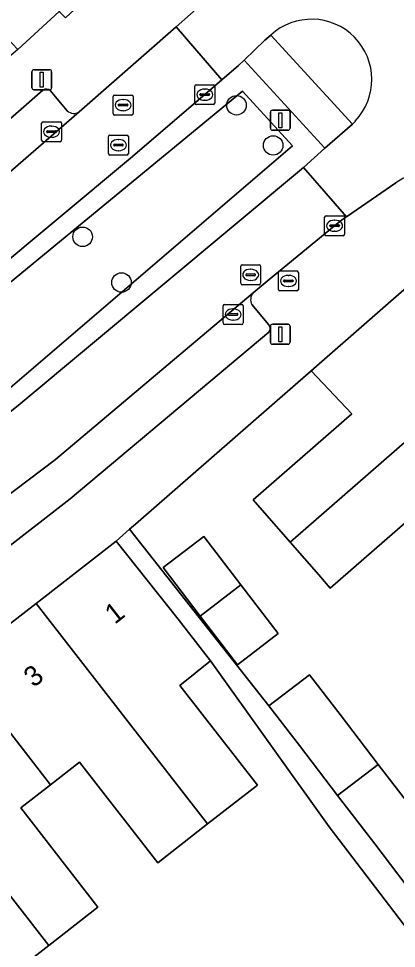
# Model space of a CAD drawing. Extents: x 159716 to 160783, y 383290 to 384031.
# Drawn here: x 160450.76 to 160469.71, y 383548.4 to 383595.01 of the extents above; entities that cross this region are included whole.
import ezdxf

# ---------------------------------------------------------------- set-up
doc = ezdxf.new("R2010")
doc.units = 0
for name, color, linetype in [('IMGEO_Boom', 7, 'Continuous'), ('IMGEO_Erf', 7, 'Continuous'), ('IMGEO_Groenvoorziening', 7, 'Continuous'), ('IMGEO_Kolk', 7, 'Continuous'), ('IMGEO_Lichtmast', 7, 'Continuous'), ('IMGEO_Muur', 7, 'Continuous'), ('IMGEO_Pand', 7, 'Continuous'), ('IMGEO_Pand_nummerreeks', 7, 'Continuous'), ('IMGEO_Parkeervlak_open', 7, 'Continuous'), ('IMGEO_Rijbaan_lokaal_open', 7, 'Continuous'), ('IMGEO_Rioolput', 7, 'Continuous'), ('IMGEO_Verkeerseiland_groen', 7, 'Continuous'), ('IMGEO_Voetpad_open', 7, 'Continuous')]:
    doc.layers.add(name, color=color, linetype=linetype)

msp = doc.modelspace()

# ---------------------------------------------------------------- linework, layer by layer
at = {"layer": 'IMGEO_Boom'}
for centre in [(160461.691, 383590.664), (160463.532, 383588.652), (160453.973, 383584.072), (160455.923, 383581.781)]:
    msp.add_circle(centre, 0.489, dxfattribs=at)
at = {"layer": 'IMGEO_Erf'}
for points in [[(160471.319, 383570.744), (160466.394, 383566.457), (160465.817, 383567.119), (160464.383, 383568.766), (160462.534, 383570.89), (160467.474, 383575.19), (160465.436, 383577.354), (160456.618, 383569.659), (160456.33, 383569.408), (160463.32, 383560.558), (160465.357, 383562.118), (160466.884, 383560.123), (160468.801, 383557.62), (160470.663, 383555.19)], [(160475.911, 383541.981), (160466.338, 383554.496), (160460.386, 383562.805), (160458.842, 383561.583), (160462.738, 383556.576), (160460.243, 383554.634), (160457.743, 383552.688), (160453.817, 383557.732), (160452.36, 383556.598), (160450.87, 383555.439), (160454.74, 383550.466), (160452.271, 383548.545), (160449.767, 383546.596), (160445.876, 383551.596), (160444.421, 383550.464), (160443.003, 383549.36), (160446.871, 383544.391)]]:
    msp.add_lwpolyline(points, dxfattribs=at)
msp.add_lwpolyline([(160461.741, 383562.62), (160459.876, 383565.055), (160458.011, 383567.49), (160460.047, 383569.05), (160461.912, 383566.615), (160463.777, 383564.179)], close=True, dxfattribs=at)
at = {"layer": 'IMGEO_Groenvoorziening'}
for points in [[(160441.098, 383568.136), (160443.878, 383570.259), (160449.157, 383574.362), (160450.745, 383575.611), (160465.056, 383587.54), (160466.119, 383588.51), (160462.076, 383592.933), (160461.787, 383592.665), (160460.963, 383591.947), (160460.102, 383591.197), (160456.376, 383588.007), (160445.683, 383579.106), (160439.333, 383574.187), (160436.59, 383572.062), (160419.524, 383558.843), (160420.216, 383557.971), (160438.33, 383572.13), (160446.182, 383578.368), (160461.987, 383591.376), (160464.497, 383588.63), (160449.031, 383575.404), (160429.985, 383560.714), (160408.787, 383544.408), (160399.76, 383538.598)], [(160461.987, 383591.376), (160446.182, 383578.368), (160438.33, 383572.13), (160420.216, 383557.971), (160419.524, 383558.843), (160417.152, 383557.006), (160417.838, 383556.217), (160406.387, 383547.75), (160398.414, 383542.841)], [(160399.76, 383538.598), (160408.787, 383544.408), (160429.985, 383560.714), (160449.031, 383575.404), (160464.497, 383588.63), (160461.987, 383591.376)]]:
    msp.add_lwpolyline(points, dxfattribs=at)
at = {"layer": 'IMGEO_Kolk'}
for p, q in [((160459.676, 383591.697), (160460.528, 383591.697)), ((160459.601, 383590.771), (160459.601, 383591.623)), ((160459.903, 383591.24), (160460.301, 383591.24)), ((160460.089, 383591.477), (160460.114, 383591.477)), ((160460.602, 383591.623), (160460.602, 383590.771)), ((160459.86, 383591.191), (160459.86, 383591.203)), ((160460.298, 383591.154), (160459.9, 383591.154)), ((160460.112, 383590.917), (160460.087, 383590.917)), ((160460.344, 383591.203), (160460.344, 383591.191)), ((160460.528, 383590.697), (160459.676, 383590.697)), ((160451.989, 383589.839), (160452.841, 383589.839)), ((160451.914, 383588.913), (160451.914, 383589.765)), ((160452.216, 383589.382), (160452.614, 383589.382)), ((160452.402, 383589.619), (160452.427, 383589.619)), ((160452.915, 383589.765), (160452.915, 383588.913)), ((160452.173, 383589.333), (160452.173, 383589.345)), ((160452.611, 383589.296), (160452.213, 383589.296)), ((160452.425, 383589.059), (160452.4, 383589.059)), ((160452.657, 383589.345), (160452.657, 383589.333)), ((160452.841, 383588.839), (160451.989, 383588.839)), ((160466.113, 383584.2), (160466.113, 383585.052)), ((160466.188, 383585.126), (160467.04, 383585.126)), ((160466.601, 383584.906), (160466.626, 383584.906)), ((160467.114, 383585.052), (160467.114, 383584.2)), ((160466.372, 383584.62), (160466.372, 383584.632)), ((160466.81, 383584.583), (160466.412, 383584.583)), ((160466.415, 383584.669), (160466.813, 383584.669)), ((160466.624, 383584.346), (160466.599, 383584.346)), ((160466.856, 383584.632), (160466.856, 383584.62)), ((160467.04, 383584.126), (160466.188, 383584.126)), ((160461.023, 383579.75), (160461.023, 383580.602)), ((160461.098, 383580.676), (160461.95, 383580.676)), ((160462.024, 383580.602), (160462.024, 383579.75)), ((160461.282, 383580.17), (160461.282, 383580.182)), ((160461.72, 383580.133), (160461.322, 383580.133)), ((160461.325, 383580.219), (160461.723, 383580.219)), ((160461.511, 383580.456), (160461.536, 383580.456)), ((160461.766, 383580.182), (160461.766, 383580.17)), ((160461.95, 383579.676), (160461.098, 383579.676)), ((160461.534, 383579.896), (160461.509, 383579.896))]:
    msp.add_line(p, q, dxfattribs=at)
for points in [[(160459.676, 383591.697), (160460.528, 383591.697)], [(160459.601, 383590.771), (160459.601, 383591.623)], [(160460.602, 383591.623), (160460.602, 383590.771)], [(160460.528, 383590.697), (160459.676, 383590.697)], [(160451.989, 383589.839), (160452.841, 383589.839)], [(160451.914, 383588.913), (160451.914, 383589.765)], [(160452.915, 383589.765), (160452.915, 383588.913)], [(160452.841, 383588.839), (160451.989, 383588.839)], [(160466.113, 383584.2), (160466.113, 383585.052)], [(160466.188, 383585.126), (160467.04, 383585.126)], [(160467.114, 383585.052), (160467.114, 383584.2)], [(160467.04, 383584.126), (160466.188, 383584.126)], [(160461.023, 383579.75), (160461.023, 383580.602)], [(160461.098, 383580.676), (160461.95, 383580.676)], [(160462.024, 383580.602), (160462.024, 383579.75)], [(160461.95, 383579.676), (160461.098, 383579.676)]]:
    msp.add_lwpolyline(points, dxfattribs=at)
for centre, radius, start, end in [((160459.678, 383591.621), 0.0765, 91.552, 178.448), ((160459.678, 383591.621), 0.0765, 91.552, 178.448), ((160460.526, 383591.621), 0.0765, 1.552, 88.448), ((160460.526, 383591.621), 0.0765, 1.552, 88.448), ((160459.9, 383591.2), 0.0403, 85.8775, 175.7526), ((160460.305, 383591.202), 0.0386, 1.7309, 96.639), ((160459.678, 383590.773), 0.0765, 181.552, 268.448), ((160459.678, 383590.773), 0.0765, 181.552, 268.448), ((160459.897, 383591.19), 0.0366, 178.938, 274.7102), ((160460.301, 383591.197), 0.043, 264.8664, 352.4533), ((160460.526, 383590.773), 0.0765, 271.552, 358.448), ((160460.526, 383590.773), 0.0765, 271.552, 358.448), ((160451.991, 383589.763), 0.0765, 91.552, 178.448), ((160451.991, 383589.763), 0.0765, 91.552, 178.448), ((160452.839, 383589.763), 0.0765, 1.552, 88.448), ((160452.839, 383589.763), 0.0765, 1.552, 88.448), ((160452.213, 383589.342), 0.0403, 85.8775, 175.7526), ((160452.618, 383589.344), 0.0386, 1.7309, 96.639), ((160451.991, 383588.915), 0.0765, 181.552, 268.448), ((160451.991, 383588.915), 0.0765, 181.552, 268.448), ((160452.21, 383589.332), 0.0366, 178.938, 274.7102), ((160452.614, 383589.339), 0.043, 264.8664, 352.4533), ((160452.839, 383588.915), 0.0765, 271.552, 358.448), ((160452.839, 383588.915), 0.0765, 271.552, 358.448), ((160466.19, 383585.05), 0.0765, 91.552, 178.448), ((160466.19, 383585.05), 0.0765, 91.552, 178.448), ((160467.038, 383585.05), 0.0765, 1.552, 88.448), ((160467.038, 383585.05), 0.0765, 1.552, 88.448), ((160466.412, 383584.629), 0.0403, 85.8775, 175.7526), ((160466.409, 383584.619), 0.0366, 178.938, 274.7102), ((160466.813, 383584.626), 0.043, 264.8664, 352.4533), ((160466.817, 383584.631), 0.0386, 1.7309, 96.639), ((160466.19, 383584.202), 0.0765, 181.552, 268.448), ((160466.19, 383584.202), 0.0765, 181.552, 268.448), ((160467.038, 383584.202), 0.0765, 271.552, 358.448), ((160467.038, 383584.202), 0.0765, 271.552, 358.448), ((160461.1, 383580.6), 0.0765, 91.552, 178.448), ((160461.1, 383580.6), 0.0765, 91.552, 178.448), ((160461.948, 383580.6), 0.0765, 1.552, 88.448), ((160461.948, 383580.6), 0.0765, 1.552, 88.448), ((160461.322, 383580.179), 0.0403, 85.8775, 175.7526), ((160461.319, 383580.169), 0.0366, 178.938, 274.7102), ((160461.723, 383580.176), 0.043, 264.8664, 352.4533), ((160461.727, 383580.181), 0.0386, 1.7309, 96.639), ((160461.1, 383579.752), 0.0765, 181.552, 268.448), ((160461.1, 383579.752), 0.0765, 181.552, 268.448), ((160461.948, 383579.752), 0.0765, 271.552, 358.448), ((160461.948, 383579.752), 0.0765, 271.552, 358.448)]:
    msp.add_arc(centre, radius, start, end, dxfattribs=at)
for centre, major_axis, ratio, start_param, end_param in [((160460.088, 383591.197), (-0.387, 0.002), 0.722429, 4.712389, 7.853982), ((160460.113, 383591.197), (-0.39, 0.002), 0.717154, 1.570796, 4.712389), ((160452.401, 383589.339), (-0.387, 0.002), 0.722429, 4.712389, 7.853982), ((160452.426, 383589.339), (-0.39, 0.002), 0.717154, 1.570796, 4.712389), ((160466.6, 383584.626), (-0.387, 0.002), 0.722429, 4.712389, 7.853982), ((160466.625, 383584.626), (-0.39, 0.002), 0.717154, 1.570796, 4.712389), ((160461.51, 383580.176), (-0.387, 0.002), 0.722429, 4.712389, 7.853982), ((160461.535, 383580.176), (-0.39, 0.002), 0.717154, 1.570796, 4.712389)]:
    msp.add_ellipse(centre, major_axis=major_axis, ratio=ratio, start_param=start_param, end_param=end_param, dxfattribs=at)
at = {"layer": 'IMGEO_Lichtmast'}
for p, q in [((160451.43, 383591.546), (160451.43, 383592.346)), ((160451.43, 383592.346), (160451.43, 383591.546)), ((160451.53, 383592.446), (160452.32, 383592.446)), ((160452.32, 383592.446), (160451.53, 383592.446)), ((160452.42, 383592.346), (160452.42, 383591.546)), ((160452.42, 383591.546), (160452.42, 383592.346)), ((160452.32, 383591.446), (160451.53, 383591.446)), ((160451.53, 383591.446), (160452.32, 383591.446)), ((160463.39, 383589.516), (160463.39, 383590.316)), ((160463.39, 383590.316), (160463.39, 383589.516)), ((160463.49, 383590.416), (160464.28, 383590.416)), ((160464.28, 383590.416), (160463.49, 383590.416)), ((160464.38, 383590.316), (160464.38, 383589.516)), ((160464.38, 383589.516), (160464.38, 383590.316)), ((160464.28, 383589.416), (160463.49, 383589.416)), ((160463.49, 383589.416), (160464.28, 383589.416)), ((160463.391, 383578.788), (160463.391, 383579.588)), ((160463.391, 383579.588), (160463.391, 383578.788)), ((160463.491, 383579.688), (160464.281, 383579.688)), ((160464.281, 383579.688), (160463.491, 383579.688)), ((160464.381, 383579.588), (160464.381, 383578.788)), ((160464.381, 383578.788), (160464.381, 383579.588)), ((160464.281, 383578.688), (160463.491, 383578.688)), ((160463.491, 383578.688), (160464.281, 383578.688))]:
    msp.add_line(p, q, dxfattribs=at)
for points in [[(160451.85, 383592.321), (160452, 383592.321), (160452, 383591.571), (160451.85, 383591.571), (160451.85, 383592.321)], [(160463.81, 383590.291), (160463.96, 383590.291), (160463.96, 383589.541), (160463.81, 383589.541), (160463.81, 383590.291)], [(160463.811, 383579.563), (160463.961, 383579.563), (160463.961, 383578.813), (160463.811, 383578.813), (160463.811, 383579.563)]]:
    msp.add_lwpolyline(points, dxfattribs=at)
for centre, start, end in [((160451.53, 383592.346), 90, 180), ((160451.53, 383592.346), 90, 180), ((160452.32, 383592.346), 0, 90), ((160452.32, 383592.346), 360, 90), ((160451.53, 383591.546), 180, 270), ((160451.53, 383591.546), 180, 270), ((160452.32, 383591.546), 270, 0), ((160452.32, 383591.546), 270, 0), ((160463.49, 383590.316), 90, 180), ((160463.49, 383590.316), 90, 180), ((160464.28, 383590.316), 0, 90), ((160464.28, 383590.316), 360, 90), ((160463.49, 383589.516), 180, 270), ((160463.49, 383589.516), 180, 270), ((160464.28, 383589.516), 270, 0), ((160464.28, 383589.516), 270, 0), ((160463.491, 383579.588), 90, 180), ((160463.491, 383579.588), 90, 180), ((160464.281, 383579.588), 0, 90), ((160464.281, 383579.588), 360, 90), ((160463.491, 383578.788), 180, 270), ((160463.491, 383578.788), 180, 270), ((160464.281, 383578.788), 270, 0), ((160464.281, 383578.788), 270, 0)]:
    msp.add_arc(centre, 0.1, start, end, dxfattribs=at)
at = {"layer": 'IMGEO_Muur'}
msp.add_lwpolyline([(160465.53, 383577.422), (160456.618, 383569.659)], dxfattribs=at)
at = {"layer": 'IMGEO_Pand'}
for points in [[(160456.328, 383598.598), (160452.391, 383602.844), (160441.972, 383593.226), (160443.909, 383591.127), (160448.722, 383595.569), (160450.731, 383593.456), (160452.802, 383595.359)], [(160474.958, 383577.974), (160471.15, 383582.344), (160465.436, 383577.354), (160467.474, 383575.19), (160462.534, 383570.89), (160464.383, 383568.766)], [(160478.672, 383573.711), (160474.958, 383577.974), (160464.383, 383568.766), (160465.817, 383567.119), (160466.394, 383566.457), (160471.319, 383570.744), (160473.02, 383568.79)], [(160459.876, 383565.055), (160461.912, 383566.615), (160460.047, 383569.05), (160458.011, 383567.49)], [(160460.386, 383562.805), (160458.759, 383564.903), (160455.652, 383568.805), (160451.637, 383565.693), (160460.243, 383554.634), (160462.738, 383556.576), (160458.842, 383561.583)], [(160461.912, 383566.615), (160459.876, 383565.055), (160461.741, 383562.62), (160463.777, 383564.179)], [(160451.637, 383565.693), (160447.673, 383562.621), (160452.36, 383556.598), (160453.817, 383557.732), (160457.743, 383552.688), (160460.243, 383554.634)], [(160452.36, 383556.598), (160447.673, 383562.621), (160443.709, 383559.549), (160452.271, 383548.545), (160454.74, 383550.466), (160450.87, 383555.439)], [(160463.32, 383560.558), (160464.848, 383558.563), (160466.765, 383556.06), (160468.801, 383557.62), (160466.884, 383560.123), (160465.357, 383562.118)], [(160443.709, 383559.549), (160439.743, 383556.475), (160444.421, 383550.464), (160445.876, 383551.596), (160449.767, 383546.596), (160452.271, 383548.545)], [(160468.801, 383557.62), (160466.765, 383556.06), (160468.627, 383553.63), (160470.211, 383551.561), (160472.248, 383553.121), (160470.663, 383555.19)]]:
    msp.add_lwpolyline(points, close=True, dxfattribs=at)
at = {"layer": 'IMGEO_Parkeervlak_open'}
for points in [[(160451.98, 383591.416), (160446.67, 383586.789), (160443.313, 383583.959), (160440.642, 383581.871), (160433.666, 383576.451), (160409.644, 383557.841)], [(160453.204, 383590.391), (160452.355, 383591.383)], [(160434.605, 383574.639), (160437.407, 383576.667), (160441.855, 383580.276), (160444.559, 383582.233), (160447.921, 383585.232), (160453.807, 383590.339)], [(160462.536, 383581.254), (160452.608, 383572.904), (160445.815, 383567.773), (160444.366, 383566.679), (160443.016, 383565.634), (160415.975, 383544.704)], [(160463.321, 383579.661), (160462.468, 383580.674)], [(160417.362, 383543.071), (160445.968, 383565.216), (160453.348, 383570.928), (160463.309, 383579.284)]]:
    msp.add_lwpolyline(points, dxfattribs=at)
for centre, radius, start, end in [((160452.15, 383591.204), 0.272, 41.116, 128.8259), ((160453.538, 383590.741), 0.484, 226.3471, 303.7955), ((160462.878, 383580.92), 0.478, 135.6807, 210.9455), ((160463.094, 383579.48), 0.29, 317.6692, 38.6845)]:
    msp.add_arc(centre, radius, start, end, dxfattribs=at)
at = {"layer": 'IMGEO_Rijbaan_lokaal_open'}
for points in [[(160460.103, 383595.872), (160458.661, 383594.596), (160460.963, 383591.947), (160461.787, 383592.665), (160462.076, 383592.933), (160463.114, 383593.925), (160463.409, 383594.184)], [(160467.653, 383589.872), (160467.507, 383589.719), (160466.119, 383588.51), (160465.056, 383587.54), (160467.208, 383585.075), (160469.692, 383586.773)]]:
    msp.add_lwpolyline(points, dxfattribs=at)
for points in [[(160460.963, 383591.947), (160458.661, 383594.596), (160453.807, 383590.339), (160447.921, 383585.232), (160444.559, 383582.233), (160441.855, 383580.276), (160437.407, 383576.667), (160439.333, 383574.187), (160445.683, 383579.106), (160456.376, 383588.007), (160460.102, 383591.197)], [(160462.536, 383581.254), (160463.326, 383581.931), (160466.614, 383584.626), (160466.966, 383584.91), (160467.208, 383585.075), (160465.056, 383587.54), (160450.745, 383575.611), (160449.157, 383574.362), (160443.878, 383570.259), (160445.815, 383567.773), (160452.608, 383572.904)]]:
    msp.add_lwpolyline(points, close=True, dxfattribs=at)
for centre, radius, start, end in [((160465.454, 383591.952), 3.027, 316.5846, 132.5047), ((160472.446, 383582.832), 4.808, 49.1527, 124.9472)]:
    msp.add_arc(centre, radius, start, end, dxfattribs=at)
at = {"layer": 'IMGEO_Rioolput'}
for p, q in [((160455.506, 383590.248), (160455.506, 383591.1)), ((160455.581, 383591.174), (160456.433, 383591.174)), ((160455.994, 383590.954), (160456.019, 383590.954)), ((160456.507, 383591.1), (160456.507, 383590.248)), ((160455.765, 383590.668), (160455.765, 383590.68)), ((160456.203, 383590.631), (160455.805, 383590.631)), ((160455.808, 383590.717), (160456.206, 383590.717)), ((160456.017, 383590.394), (160455.992, 383590.394)), ((160456.249, 383590.68), (160456.249, 383590.668)), ((160456.433, 383590.174), (160455.581, 383590.174)), ((160455.27, 383588.241), (160455.27, 383589.093)), ((160455.345, 383589.167), (160456.197, 383589.167)), ((160455.758, 383588.947), (160455.783, 383588.947)), ((160456.271, 383589.093), (160456.271, 383588.241)), ((160455.529, 383588.661), (160455.529, 383588.673)), ((160455.967, 383588.624), (160455.569, 383588.624)), ((160455.572, 383588.71), (160455.97, 383588.71)), ((160456.013, 383588.673), (160456.013, 383588.661)), ((160456.197, 383588.167), (160455.345, 383588.167)), ((160455.781, 383588.387), (160455.756, 383588.387)), ((160461.903, 383581.739), (160461.903, 383582.591)), ((160461.978, 383582.665), (160462.83, 383582.665)), ((160462.391, 383582.445), (160462.416, 383582.445)), ((160462.904, 383582.591), (160462.904, 383581.739)), ((160463.872, 383582.359), (160464.724, 383582.359)), ((160462.162, 383582.159), (160462.162, 383582.171)), ((160462.6, 383582.122), (160462.202, 383582.122)), ((160462.205, 383582.208), (160462.603, 383582.208)), ((160462.646, 383582.171), (160462.646, 383582.159)), ((160463.797, 383581.433), (160463.797, 383582.285)), ((160464.099, 383581.902), (160464.497, 383581.902)), ((160464.285, 383582.139), (160464.31, 383582.139)), ((160464.798, 383582.285), (160464.798, 383581.433)), ((160462.83, 383581.665), (160461.978, 383581.665)), ((160462.414, 383581.885), (160462.389, 383581.885)), ((160464.056, 383581.853), (160464.056, 383581.865)), ((160464.494, 383581.816), (160464.096, 383581.816)), ((160464.308, 383581.579), (160464.283, 383581.579)), ((160464.54, 383581.865), (160464.54, 383581.853)), ((160464.724, 383581.359), (160463.872, 383581.359))]:
    msp.add_line(p, q, dxfattribs=at)
for points in [[(160455.506, 383590.248), (160455.506, 383591.1)], [(160455.581, 383591.174), (160456.433, 383591.174)], [(160456.507, 383591.1), (160456.507, 383590.248)], [(160456.433, 383590.174), (160455.581, 383590.174)], [(160455.27, 383588.241), (160455.27, 383589.093)], [(160455.345, 383589.167), (160456.197, 383589.167)], [(160456.271, 383589.093), (160456.271, 383588.241)], [(160456.197, 383588.167), (160455.345, 383588.167)], [(160461.903, 383581.739), (160461.903, 383582.591)], [(160461.978, 383582.665), (160462.83, 383582.665)], [(160462.904, 383582.591), (160462.904, 383581.739)], [(160463.872, 383582.359), (160464.724, 383582.359)], [(160463.797, 383581.433), (160463.797, 383582.285)], [(160464.798, 383582.285), (160464.798, 383581.433)], [(160462.83, 383581.665), (160461.978, 383581.665)], [(160464.724, 383581.359), (160463.872, 383581.359)]]:
    msp.add_lwpolyline(points, dxfattribs=at)
for centre, radius, start, end in [((160455.583, 383591.098), 0.0765, 91.552, 178.448), ((160455.583, 383591.098), 0.0765, 91.552, 178.448), ((160456.431, 383591.098), 0.0765, 1.552, 88.448), ((160456.431, 383591.098), 0.0765, 1.552, 88.448), ((160455.805, 383590.677), 0.0403, 85.8775, 175.7526), ((160455.802, 383590.667), 0.0366, 178.938, 274.7102), ((160456.206, 383590.674), 0.043, 264.8664, 352.4533), ((160456.21, 383590.679), 0.0386, 1.7309, 96.639), ((160455.583, 383590.25), 0.0765, 181.552, 268.448), ((160455.583, 383590.25), 0.0765, 181.552, 268.448), ((160456.431, 383590.25), 0.0765, 271.552, 358.448), ((160456.431, 383590.25), 0.0765, 271.552, 358.448), ((160455.347, 383589.091), 0.0765, 91.552, 178.448), ((160455.347, 383589.091), 0.0765, 91.552, 178.448), ((160456.195, 383589.091), 0.0765, 1.552, 88.448), ((160456.195, 383589.091), 0.0765, 1.552, 88.448), ((160455.569, 383588.67), 0.0403, 85.8775, 175.7526), ((160455.566, 383588.66), 0.0366, 178.938, 274.7102), ((160455.97, 383588.667), 0.043, 264.8664, 352.4533), ((160455.974, 383588.672), 0.0386, 1.7309, 96.639), ((160455.347, 383588.243), 0.0765, 181.552, 268.448), ((160455.347, 383588.243), 0.0765, 181.552, 268.448), ((160456.195, 383588.243), 0.0765, 271.552, 358.448), ((160456.195, 383588.243), 0.0765, 271.552, 358.448), ((160461.98, 383582.589), 0.0765, 91.552, 178.448), ((160461.98, 383582.589), 0.0765, 91.552, 178.448), ((160462.828, 383582.589), 0.0765, 1.552, 88.448), ((160462.828, 383582.589), 0.0765, 1.552, 88.448), ((160463.874, 383582.283), 0.0765, 91.552, 178.448), ((160463.874, 383582.283), 0.0765, 91.552, 178.448), ((160464.722, 383582.283), 0.0765, 1.552, 88.448), ((160464.722, 383582.283), 0.0765, 1.552, 88.448), ((160462.202, 383582.168), 0.0403, 85.8775, 175.7526), ((160462.199, 383582.158), 0.0366, 178.938, 274.7102), ((160462.603, 383582.165), 0.043, 264.8664, 352.4533), ((160462.607, 383582.17), 0.0386, 1.7309, 96.639), ((160464.096, 383581.862), 0.0403, 85.8775, 175.7526), ((160464.501, 383581.864), 0.0386, 1.7309, 96.639), ((160461.98, 383581.741), 0.0765, 181.552, 268.448), ((160461.98, 383581.741), 0.0765, 181.552, 268.448), ((160462.828, 383581.741), 0.0765, 271.552, 358.448), ((160462.828, 383581.741), 0.0765, 271.552, 358.448), ((160463.874, 383581.435), 0.0765, 181.552, 268.448), ((160463.874, 383581.435), 0.0765, 181.552, 268.448), ((160464.093, 383581.852), 0.0366, 178.938, 274.7102), ((160464.497, 383581.859), 0.043, 264.8664, 352.4533), ((160464.722, 383581.435), 0.0765, 271.552, 358.448), ((160464.722, 383581.435), 0.0765, 271.552, 358.448)]:
    msp.add_arc(centre, radius, start, end, dxfattribs=at)
for centre, major_axis, ratio, start_param, end_param in [((160455.993, 383590.674), (-0.387, 0.002), 0.722429, 4.712389, 7.853982), ((160456.018, 383590.674), (-0.39, 0.002), 0.717154, 1.570796, 4.712389), ((160455.757, 383588.667), (-0.387, 0.002), 0.722429, 4.712389, 7.853982), ((160455.782, 383588.667), (-0.39, 0.002), 0.717154, 1.570796, 4.712389), ((160462.39, 383582.165), (-0.387, 0.002), 0.722429, 4.712389, 7.853982), ((160462.415, 383582.165), (-0.39, 0.002), 0.717154, 1.570796, 4.712389), ((160464.284, 383581.859), (-0.387, 0.002), 0.722429, 4.712389, 7.853982), ((160464.309, 383581.859), (-0.39, 0.002), 0.717154, 1.570796, 4.712389)]:
    msp.add_ellipse(centre, major_axis=major_axis, ratio=ratio, start_param=start_param, end_param=end_param, dxfattribs=at)
at = {"layer": 'IMGEO_Verkeerseiland_groen'}
msp.add_lwpolyline([(160463.409, 383594.184), (160467.507, 383589.719), (160467.653, 383589.872)], dxfattribs=at)
msp.add_arc((160465.454, 383591.952), 3.027, 316.5846, 132.5047, dxfattribs=at)
at = {"layer": 'IMGEO_Voetpad_open'}
for points in [[(160460.737, 383602.65), (160458.067, 383600.195), (160456.328, 383598.598), (160456.612, 383598.292), (160453.108, 383595.041), (160452.802, 383595.359), (160450.731, 383593.456), (160441.855, 383585.964), (160441.255, 383585.461), (160440.303, 383584.74), (160436.244, 383581.593), (160432.28, 383578.52), (160428.315, 383575.447), (160424.351, 383572.374), (160420.387, 383569.299), (160416.422, 383566.226), (160412.458, 383563.153)], [(160453.807, 383590.339), (160458.661, 383594.596), (160460.103, 383595.872)], [(160433.666, 383576.451), (160440.642, 383581.871), (160443.313, 383583.959), (160446.67, 383586.789), (160451.98, 383591.416)], [(160452.355, 383591.383), (160453.204, 383590.391)], [(160469.692, 383586.773), (160467.208, 383585.075), (160466.966, 383584.91), (160466.614, 383584.626), (160463.326, 383581.931), (160462.536, 383581.254)], [(160443.709, 383559.549), (160447.673, 383562.621), (160451.637, 383565.693), (160455.652, 383568.805), (160456.33, 383569.408), (160456.618, 383569.659), (160465.436, 383577.354), (160471.15, 383582.344), (160472.825, 383583.793), (160475.727, 383586.349), (160475.591, 383586.469)], [(160462.468, 383580.674), (160463.321, 383579.661)], [(160463.309, 383579.284), (160453.348, 383570.928), (160445.968, 383565.216), (160417.362, 383543.071)], [(160470.211, 383551.561), (160468.627, 383553.63), (160466.765, 383556.06), (160464.848, 383558.563), (160463.32, 383560.558), (160456.33, 383569.408), (160455.652, 383568.805), (160458.759, 383564.903), (160460.386, 383562.805), (160466.338, 383554.496), (160475.911, 383541.981)]]:
    msp.add_lwpolyline(points, dxfattribs=at)
msp.add_lwpolyline([(160463.409, 383594.184), (160463.114, 383593.925), (160462.076, 383592.933), (160466.119, 383588.51), (160467.507, 383589.719)], close=True, dxfattribs=at)
for centre, radius, start, end in [((160452.15, 383591.204), 0.272, 41.116, 128.8259), ((160453.538, 383590.741), 0.484, 226.3471, 303.7955), ((160472.446, 383582.832), 4.808, 49.1527, 124.9472), ((160462.878, 383580.92), 0.478, 135.6807, 210.9455), ((160463.094, 383579.48), 0.29, 317.6692, 38.6845)]:
    msp.add_arc(centre, radius, start, end, dxfattribs=at)

# ---------------------------------------------------------------- texts
at = {"layer": 'IMGEO_Pand_nummerreeks'}
for s, p in [('1', (160455.585, 383564.613)), ('3', (160451.516, 383561.446))]:
    msp.add_text(s, height=1, rotation=37.8897, dxfattribs=at).set_placement(p)

doc.saveas('drawing.dxf')
